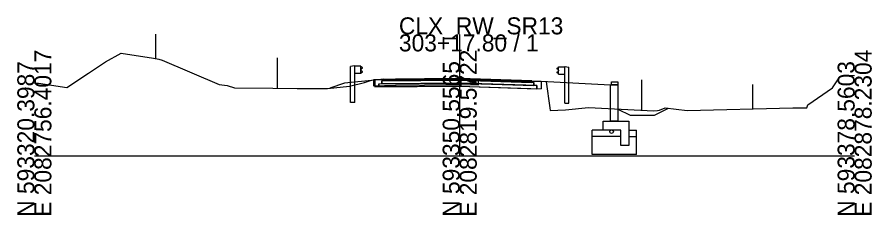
# Model space of a CAD drawing. Extents: x -26 to 2138, y -10 to 4518.
# Drawn here: x 997.2 to 1137.8, y 1490.3 to 1522.8 of the extents above; entities that cross this region are included whole.
import ezdxf

# ---------------------------------------------------------------- set-up
doc = ezdxf.new("R2010")
doc.units = 0
for name, color, linetype in [('GK_Cells', 7, 'Continuous'), ('MD_P_Surface_Aggregate_Base', 7, 'Continuous'), ('MD_P_Surface_Asphalt_Concrete_Base', 7, 'Continuous'), ('MD_P_Surface_Asphalt_Concrete_Intermediate_Course', 7, 'Continuous'), ('MD_P_Surface_Asphalt_Concrete_Surface_Course', 7, 'Continuous'), ('MD_P_Surface_Non-Reinforced_Concrete_Pavement', 7, 'Continuous'), ('MD_X_Asphalt_Pavement', 7, 'Continuous'), ('RD_P_Cells', 7, 'Continuous'), ('RW_P_Esmt_SH', 7, 'Continuous'), ('RW_X_Esmt_SH', 7, 'Continuous'), ('SC_Scratch1', 7, 'Continuous'), ('UT_X_Water', 7, 'Continuous'), ('XS_P_Excavation_Limits', 7, 'Continuous'), ('XS_P_Finished_Grade', 7, 'Continuous'), ('XS_P_Subgrade', 7, 'Continuous'), ('XS_X_Ground_Line', 7, 'Continuous')]:
    doc.layers.add(name, color=color, linetype=linetype)

msp = doc.modelspace()

# ---------------------------------------------------------------- linework, layer by layer
at = {"layer": 'GK_Cells'}
for p, q in [((1070, 1500), (1070, 1520)), ((1000, 1500), (1070, 1500)), ((1070, 1500), (1135, 1500))]:
    msp.add_line(p, q, dxfattribs=at)
at = {"layer": 'MD_P_Surface_Aggregate_Base'}
for points in [[(1070, 1511.99), (1070, 1511.49), (1056.69, 1511.36), (1056.69, 1511.86), (1070, 1511.99)], [(1070, 1511.99), (1070, 1511.49), (1082.72, 1511.07), (1082.72, 1511.57), (1070, 1511.99)]]:
    msp.add_lwpolyline(points, dxfattribs=at)
at = {"layer": 'MD_P_Surface_Asphalt_Concrete_Base'}
for points in [[(1070, 1512.49), (1070, 1511.99), (1057.19, 1511.86), (1057.19, 1512.36), (1070, 1512.49)], [(1070, 1512.49), (1070, 1511.99), (1082.22, 1511.59), (1082.22, 1512.09), (1081.89, 1512.1), (1070, 1512.49)]]:
    msp.add_lwpolyline(points, dxfattribs=at)
at = {"layer": 'MD_P_Surface_Asphalt_Concrete_Intermediate_Course'}
for points in [[(1070, 1512.64), (1070, 1512.49), (1057.52, 1512.36), (1057.52, 1512.51), (1070, 1512.64)], [(1070, 1512.64), (1070, 1512.49), (1081.89, 1512.1), (1081.89, 1512.25), (1070, 1512.64)]]:
    msp.add_lwpolyline(points, dxfattribs=at)
at = {"layer": 'MD_P_Surface_Asphalt_Concrete_Surface_Course'}
for points in [[(1070, 1512.74), (1070, 1512.64), (1057.52, 1512.51), (1057.52, 1512.61), (1070, 1512.74)], [(1070, 1512.74), (1070, 1512.64), (1081.89, 1512.25), (1081.89, 1512.35), (1070, 1512.74)]]:
    msp.add_lwpolyline(points, dxfattribs=at)
at = {"layer": 'MD_P_Surface_Non-Reinforced_Concrete_Pavement'}
for points in [[(1096.04, 1505.72), (1095.05, 1505.72), (1094.81, 1505.71), (1094.81, 1511.71), (1095.05, 1511.72), (1096.04, 1511.72), (1096.04, 1505.72)], [(1096.04, 1511.72), (1095.01, 1511.72), (1095.01, 1512.22), (1096.04, 1512.22), (1096.04, 1511.72)], [(1097.67, 1505.72), (1097.85, 1505.72), (1097.85, 1504.83), (1097.85, 1501.72), (1097.67, 1501.72), (1096.53, 1501.72), (1096.53, 1502.89), (1096.53, 1504.22), (1095.54, 1504.22), (1093.59, 1504.22), (1093.59, 1504.79), (1093.59, 1505.72), (1097.67, 1505.72)]]:
    msp.add_lwpolyline(points, dxfattribs=at)
at = {"layer": 'MD_X_Asphalt_Pavement'}
msp.add_lwpolyline([(1059.43, 1512.61), (1055.79, 1512.52), (1055.79, 1511.56), (1059.43, 1511.65), (1059.55, 1511.66), (1064.2, 1511.72), (1069.3, 1511.77), (1069.69, 1511.77), (1070.17, 1511.78), (1073.1, 1511.69), (1073.1, 1512.65), (1070.17, 1512.74), (1069.69, 1512.73), (1069.3, 1512.73), (1064.2, 1512.67), (1059.55, 1512.62), (1059.43, 1512.61)], dxfattribs=at)
at = {"layer": 'RD_P_Cells'}
for p, q in [((1052.1, 1514.72), (1052.05, 1514.7)), ((1052.05, 1508.8), (1052.05, 1514.7)), ((1052.64, 1514.8), (1052.1, 1514.72)), ((1052.72, 1514.76), (1052.64, 1514.8)), ((1053.72, 1514.76), (1052.72, 1514.76)), ((1052.72, 1508.8), (1052.72, 1514.76)), ((1053.72, 1513.58), (1053.72, 1514.76)), ((1053.81, 1514.66), (1053.72, 1514.68)), ((1053.73, 1514.17), (1053.73, 1514.22)), ((1053.73, 1514.12), (1053.73, 1514.17)), ((1053.76, 1514.28), (1053.97, 1514.42)), ((1053.97, 1513.92), (1053.76, 1514.06)), ((1053.97, 1514.55), (1053.81, 1514.66)), ((1053.81, 1513.67), (1053.97, 1513.79)), ((1086.03, 1514.44), (1086.19, 1514.55)), ((1086.24, 1514.16), (1086.03, 1514.31)), ((1086.03, 1513.8), (1086.24, 1513.94)), ((1086.19, 1514.55), (1086.28, 1514.56)), ((1086.27, 1514.05), (1086.27, 1514.1)), ((1086.27, 1514.01), (1086.27, 1514.05)), ((1086.28, 1513.46), (1086.28, 1514.65)), ((1086.28, 1514.65), (1087.28, 1514.65)), ((1087.28, 1514.65), (1087.36, 1514.69)), ((1087.28, 1508.69), (1087.28, 1514.65)), ((1087.36, 1514.69), (1087.9, 1514.61)), ((1087.9, 1514.61), (1087.95, 1514.59)), ((1087.95, 1508.69), (1087.95, 1514.59)), ((1053.72, 1513.58), (1052.72, 1513.58)), ((1053.72, 1513.66), (1053.81, 1513.67)), ((1086.19, 1513.56), (1086.03, 1513.67)), ((1086.28, 1513.54), (1086.19, 1513.56)), ((1086.28, 1513.46), (1087.28, 1513.46)), ((1052.72, 1508.8), (1052.05, 1508.8)), ((1087.28, 1508.69), (1087.95, 1508.69))]:
    msp.add_line(p, q, dxfattribs=at)
for points in [[(1053.74, 1514.23), (1053.74, 1514.11), (1053.73, 1514.11), (1053.73, 1514.23)], [(1053.74, 1514.2), (1053.74, 1514.14), (1053.76, 1514.14), (1053.76, 1514.2)], [(1086.26, 1514.08), (1086.26, 1514.02), (1086.24, 1514.02), (1086.24, 1514.08)], [(1086.26, 1514.11), (1086.26, 1513.99), (1086.27, 1513.99), (1086.27, 1514.11)]]:
    msp.add_lwpolyline(points, close=True, dxfattribs=at)
for centre, start, end in [((1053.81, 1514.22), 124.962, 180), ((1053.81, 1514.12), 180, 235.038), ((1053.92, 1514.49), 304.962, 54.7677), ((1053.92, 1513.85), 304.962, 54.7677), ((1086.08, 1514.37), 125.2323, 235.038), ((1086.08, 1513.74), 125.2323, 235.038), ((1086.19, 1514.1), 0, 55.038), ((1086.19, 1514.01), 304.962, 0)]:
    msp.add_arc(centre, 0.0781, start, end, dxfattribs=at)
at = {"layer": 'RW_P_Esmt_SH'}
for p, q in [((1020, 1516.03), (1020, 1520.03)), ((1118.25, 1507.76), (1118.25, 1511.76))]:
    msp.add_line(p, q, dxfattribs=at)
at = {"layer": 'RW_X_Esmt_SH'}
for p, q in [((1040, 1511.14), (1040, 1516.14)), ((1100, 1507.54), (1100, 1512.54))]:
    msp.add_line(p, q, dxfattribs=at)
at = {"layer": 'SC_Scratch1'}
for p, q in [((1057.52, 1512.61), (1056.02, 1512.46)), ((1057.19, 1512.36), (1070, 1512.49)), ((1057.19, 1512.36), (1057.19, 1511.86)), ((1057.52, 1512.61), (1070, 1512.74)), ((1057.52, 1512.51), (1070, 1512.64)), ((1057.52, 1512.61), (1057.52, 1512.36)), ((1070, 1512.74), (1081.89, 1512.35)), ((1070, 1512.64), (1081.89, 1512.25)), ((1070, 1512.49), (1082.22, 1512.09)), ((1081.89, 1512.35), (1081.89, 1512.1)), ((1081.89, 1512.35), (1083.39, 1512.28)), ((1056.69, 1511.86), (1070, 1511.99)), ((1056.69, 1511.86), (1056.69, 1511.36)), ((1070, 1511.99), (1082.72, 1511.57)), ((1082.22, 1512.09), (1082.22, 1511.59)), ((1082.72, 1511.57), (1082.72, 1511.07))]:
    msp.add_line(p, q, dxfattribs=at)
at = {"layer": 'UT_X_Water'}
msp.add_circle((1095, 1504), 0.3, dxfattribs=at)
at = {"layer": 'XS_P_Excavation_Limits'}
for p, q in [((1091.82, 1500.22), (1091.82, 1504.22)), ((1093.59, 1504.22), (1091.82, 1504.22)), ((1097.85, 1504.22), (1099.12, 1504.22)), ((1099.12, 1500.22), (1099.12, 1504.22)), ((1096.53, 1503.22), (1091.82, 1503.22)), ((1097.85, 1503.22), (1099.12, 1503.22)), ((1099.12, 1500.22), (1091.82, 1500.22))]:
    msp.add_line(p, q, dxfattribs=at)
at = {"layer": 'XS_P_Finished_Grade'}
for p, q in [((1056.02, 1512.46), (1051.05, 1511.97)), ((1051.05, 1511.97), (1048.61, 1511.16)), ((1083.39, 1512.28), (1094.81, 1511.71)), ((1096.04, 1507.69), (1098.04, 1506.69)), ((1102.04, 1506.69), (1104.36, 1507.85)), ((1098.04, 1506.69), (1102.04, 1506.69))]:
    msp.add_line(p, q, dxfattribs=at)
at = {"layer": 'XS_P_Subgrade'}
for p, q in [((1056.02, 1512.46), (1056.02, 1511.35)), ((1056.02, 1511.35), (1070, 1511.49)), ((1070, 1511.49), (1083.39, 1511.05)), ((1083.39, 1512.28), (1083.39, 1511.05))]:
    msp.add_line(p, q, dxfattribs=at)
at = {"layer": 'XS_X_Ground_Line'}
msp.add_lwpolyline([(1000, 1512), (1000.09, 1512), (1000.49, 1511.98), (1000.52, 1511.99), (1000.53, 1512), (1000.55, 1511.99), (1000.66, 1511.98), (1005.34, 1511.28), (1008.89, 1513.63), (1011.72, 1515.5), (1014.29, 1516.91), (1019.63, 1516.11), (1020.46, 1515.93), (1021.06, 1515.76), (1030.42, 1511.77), (1031.72, 1511.59), (1032.93, 1511.23), (1039.26, 1511.15), (1043.25, 1511.09), (1048.25, 1511.12), (1051.89, 1511.46), (1054.31, 1512.06), (1055.33, 1512.44), (1055.79, 1512.52), (1059.43, 1512.61), (1059.55, 1512.62), (1069.3, 1512.73), (1070.17, 1512.74), (1080.04, 1512.44), (1080.69, 1512.41), (1080.92, 1512.39), (1082.09, 1512.33), (1084.2, 1512.23), (1084.25, 1512.17), (1084.83, 1507.93), (1084.9, 1507.5), (1087.4, 1507.61), (1091.19, 1508), (1101.93, 1507.44), (1102.53, 1507.49), (1102.91, 1507.56), (1103.84, 1507.91), (1107.43, 1507.49), (1124.84, 1507.92), (1127.15, 1507.92), (1127.32, 1508.42), (1131.38, 1511.21), (1132.03, 1512.21), (1132.5, 1512.94), (1133.36, 1513.27), (1135, 1513.25)], dxfattribs=at)

# ---------------------------------------------------------------- texts
msp.add_text('-', height=0.0001).set_placement((1000, 1500))
at = {"layer": 'GK_Cells'}
for s, p in [('CLX_RW_SR13', (1060, 1520)), ('303+17.80 / 1', (1060, 1517.2))]:
    msp.add_text(s, height=2.8, dxfattribs=at).set_placement(p)
for s, p in [('E 2082756.4017', (1002.8, 1490)), ('E 2082819.5722', (1072.8, 1490)), ('E 2082878.2304', (1137.8, 1490)), ('N 593320.3987', (1000, 1490)), ('N 593350.5565', (1070, 1490)), ('N 593378.5603', (1135, 1490))]:
    msp.add_text(s, height=2.8, rotation=90, dxfattribs=at).set_placement(p)

doc.saveas('drawing.dxf')
